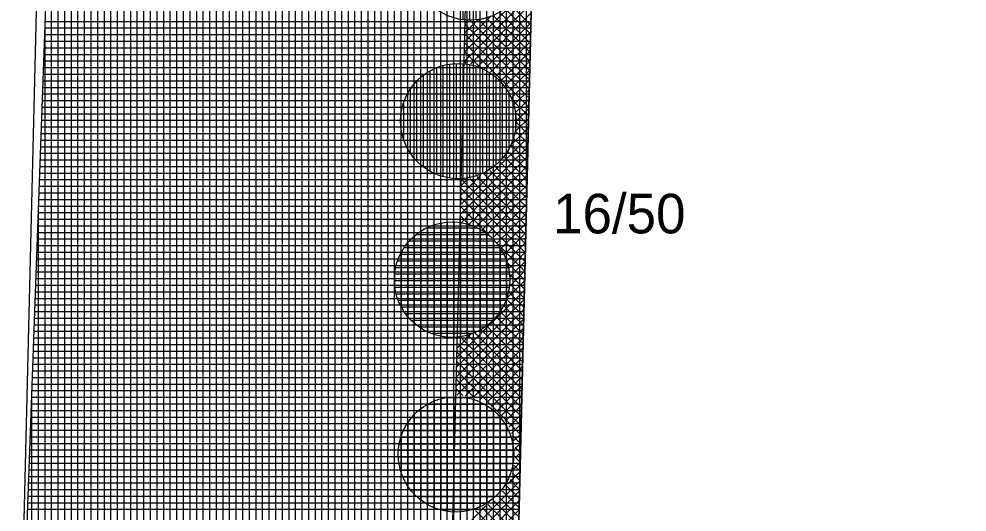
# Model space of a CAD drawing. Extents: x -565346 to -564154, y -1097386 to -1095620.
# Drawn here: x -565040.85 to -565012.1, y -1095843.05 to -1095828.1 of the extents above; entities that cross this region are included whole.
import ezdxf

# ---------------------------------------------------------------- set-up
doc = ezdxf.new("R2010")
doc.units = 0
for name, color, linetype in [('Vrstva 1', 7, 'Continuous'), ('Vrstva 40', 7, 'Continuous'), ('Vrstva 41', 7, 'Continuous'), ('Vrstva 42', 7, 'Continuous'), ('Vrstva 43', 7, 'Continuous'), ('Vrstva 44', 7, 'Continuous')]:
    doc.layers.add(name, color=color, linetype=linetype)

msp = doc.modelspace()

# ---------------------------------------------------------------- linework, layer by layer
at = {"layer": 'Vrstva 1'}
for p, q in [((-565040.85, -1095849.94), (-565040.06, -1095817.34)), ((-565025.24, -1095824.91), (-565025.81, -1095848.33))]:
    msp.add_line(p, q, dxfattribs=at)
at = {"layer": 'Vrstva 41'}
for p, q in [((-565027.342, -1095829.092), (-565025.292, -1095827.042)), ((-565027.349, -1095829.382), (-565025.299, -1095827.332)), ((-565027.142, -1095829.458), (-565025.306, -1095827.621)), ((-565025.329, -1095828.562), (-565026.12, -1095827.77)), ((-565025.322, -1095828.286), (-565025.968, -1095827.64)), ((-565027.335, -1095828.802), (-565026.531, -1095827.998)), ((-565027.328, -1095828.512), (-565026.916, -1095828.1)), ((-565027.321, -1095828.223), (-565027.216, -1095828.117)), ((-565025.362, -1095829.943), (-565027.186, -1095828.119)), ((-565026.924, -1095829.523), (-565025.313, -1095827.911)), ((-565025.356, -1095829.666), (-565026.921, -1095828.101)), ((-565025.349, -1095829.39), (-565026.688, -1095828.051)), ((-565025.342, -1095829.114), (-565026.478, -1095827.978)), ((-565025.335, -1095828.838), (-565026.29, -1095827.884)), ((-565025.369, -1095830.219), (-565027.322, -1095828.266)), ((-565026.726, -1095829.608), (-565025.32, -1095828.201)), ((-565025.376, -1095830.495), (-565027.329, -1095828.542)), ((-565026.547, -1095829.711), (-565025.327, -1095828.491)), ((-565025.382, -1095830.771), (-565027.335, -1095828.818)), ((-565026.385, -1095829.832), (-565025.334, -1095828.781)), ((-565026.907, -1095829.529), (-565027.342, -1095829.094)), ((-565026.239, -1095829.968), (-565025.341, -1095829.071)), ((-565027.285, -1095829.434), (-565027.349, -1095829.37)), ((-565026.108, -1095830.121), (-565025.348, -1095829.361)), ((-565025.994, -1095830.29), (-565025.355, -1095829.651)), ((-565025.898, -1095830.476), (-565025.362, -1095829.941)), ((-565025.823, -1095830.684), (-565025.369, -1095830.231)), ((-565025.389, -1095831.047), (-565025.859, -1095830.577)), ((-565025.771, -1095830.915), (-565025.376, -1095830.521)), ((-565025.396, -1095831.323), (-565025.764, -1095830.955)), ((-565025.747, -1095831.174), (-565025.383, -1095830.81)), ((-565025.777, -1095831.487), (-565025.39, -1095831.1)), ((-565025.403, -1095831.599), (-565025.752, -1095831.25)), ((-565025.885, -1095831.877), (-565025.398, -1095831.39)), ((-565025.409, -1095831.875), (-565025.779, -1095831.506)), ((-565027.455, -1095833.731), (-565025.405, -1095831.68)), ((-565025.416, -1095832.152), (-565025.831, -1095831.736)), ((-565027.462, -1095834.021), (-565025.412, -1095831.97)), ((-565025.43, -1095832.704), (-565026.01, -1095832.123)), ((-565025.423, -1095832.428), (-565025.911, -1095831.939)), ((-565027.444, -1095834.286), (-565025.419, -1095832.26)), ((-565025.443, -1095833.256), (-565026.259, -1095832.44)), ((-565025.436, -1095832.98), (-565026.126, -1095832.29)), ((-565027.214, -1095834.338), (-565025.426, -1095832.55)), ((-565025.456, -1095833.808), (-565026.572, -1095832.693)), ((-565025.45, -1095833.532), (-565026.407, -1095832.575)), ((-565027.448, -1095833.441), (-565026.841, -1095832.833)), ((-565027.441, -1095833.151), (-565027.236, -1095832.946)), ((-565025.483, -1095834.913), (-565027.429, -1095832.967)), ((-565025.477, -1095834.637), (-565027.177, -1095832.937)), ((-565027.006, -1095834.413), (-565025.433, -1095832.84)), ((-565025.47, -1095834.361), (-565026.954, -1095832.877)), ((-565025.463, -1095834.084), (-565026.754, -1095832.794)), ((-565025.49, -1095835.189), (-565027.443, -1095833.236)), ((-565026.821, -1095834.51), (-565025.44, -1095833.13)), ((-565025.497, -1095835.465), (-565027.45, -1095833.512)), ((-565026.653, -1095834.625), (-565025.447, -1095833.42)), ((-565025.503, -1095835.741), (-565027.457, -1095833.788)), ((-565026.502, -1095834.757), (-565025.454, -1095833.709)), ((-565027.181, -1095834.347), (-565027.463, -1095834.064)), ((-565026.366, -1095834.905), (-565025.461, -1095833.999)), ((-565026.248, -1095835.069), (-565025.468, -1095834.289)), ((-565026.146, -1095835.25), (-565025.475, -1095834.579)), ((-565026.064, -1095835.451), (-565025.482, -1095834.869)), ((-565026.005, -1095835.675), (-565025.489, -1095835.159)), ((-565025.51, -1095836.017), (-565026.057, -1095835.471)), ((-565025.976, -1095835.929), (-565025.496, -1095835.449)), ((-565025.996, -1095836.231), (-565025.503, -1095835.739)), ((-565025.517, -1095836.293), (-565025.982, -1095835.829)), ((-565026.079, -1095836.597), (-565025.51, -1095836.029)), ((-565025.524, -1095836.569), (-565025.983, -1095836.11)), ((-565027.568, -1095838.369), (-565025.518, -1095836.319)), ((-565025.53, -1095836.846), (-565026.01, -1095836.366)), ((-565027.575, -1095838.659), (-565025.525, -1095836.608)), ((-565025.544, -1095837.398), (-565026.159, -1095836.783)), ((-565025.537, -1095837.122), (-565026.074, -1095836.585)), ((-565027.582, -1095838.949), (-565025.532, -1095836.898)), ((-565025.551, -1095837.674), (-565026.262, -1095836.962)), ((-565027.589, -1095839.239), (-565025.539, -1095837.188)), ((-565025.564, -1095838.226), (-565026.521, -1095837.27)), ((-565025.557, -1095837.95), (-565026.383, -1095837.124)), ((-565027.57, -1095839.502), (-565025.546, -1095837.478)), ((-565027.561, -1095838.079), (-565027.121, -1095837.639)), ((-565025.584, -1095839.055), (-565027.033, -1095837.605)), ((-565025.577, -1095838.778), (-565026.844, -1095837.512)), ((-565025.571, -1095838.502), (-565026.673, -1095837.4)), ((-565025.604, -1095839.883), (-565027.557, -1095837.93)), ((-565027.554, -1095837.789), (-565027.495, -1095837.73)), ((-565025.598, -1095839.607), (-565027.477, -1095837.727)), ((-565027.311, -1095839.526), (-565025.553, -1095837.768)), ((-565025.591, -1095839.331), (-565027.243, -1095837.678)), ((-565025.611, -1095840.159), (-565027.564, -1095838.206)), ((-565027.079, -1095839.578), (-565025.56, -1095838.058)), ((-565025.618, -1095840.435), (-565027.571, -1095838.482)), ((-565026.872, -1095839.653), (-565025.567, -1095838.348)), ((-565025.624, -1095840.711), (-565027.578, -1095838.758)), ((-565026.684, -1095839.747), (-565025.574, -1095838.638)), ((-565027.025, -1095839.594), (-565027.584, -1095839.034)), ((-565026.514, -1095839.861), (-565025.581, -1095838.928)), ((-565027.388, -1095839.514), (-565027.591, -1095839.31)), ((-565026.361, -1095839.99), (-565025.588, -1095839.218)), ((-565026.223, -1095840.135), (-565025.595, -1095839.507)), ((-565026.101, -1095840.296), (-565025.602, -1095839.797)), ((-565025.996, -1095840.474), (-565025.609, -1095840.087)), ((-565025.909, -1095840.67), (-565025.616, -1095840.377)), ((-565025.631, -1095840.987), (-565025.884, -1095840.735)), ((-565025.842, -1095840.885), (-565025.623, -1095840.667)), ((-565025.638, -1095841.263), (-565025.804, -1095841.098)), ((-565025.8, -1095841.127), (-565025.63, -1095840.957)), ((-565025.802, -1095841.412), (-565025.638, -1095841.247)), ((-565025.645, -1095841.54), (-565025.799, -1095841.385)), ((-565025.846, -1095841.738), (-565025.645, -1095841.537)), ((-565025.651, -1095841.816), (-565025.826, -1095841.641)), ((-565026.034, -1095842.209), (-565025.652, -1095841.827)), ((-565025.658, -1095842.092), (-565025.882, -1095841.868)), ((-565027.709, -1095844.167), (-565025.659, -1095842.117)), ((-565025.665, -1095842.368), (-565025.963, -1095842.069)), ((-565027.688, -1095844.429), (-565025.666, -1095842.406)), ((-565025.678, -1095842.92), (-565026.18, -1095842.419)), ((-565025.672, -1095842.644), (-565026.063, -1095842.253)), ((-565027.403, -1095844.427), (-565025.673, -1095842.696)), ((-565025.698, -1095843.749), (-565026.625, -1095842.822)), ((-565025.692, -1095843.472), (-565026.461, -1095842.704)), ((-565025.685, -1095843.196), (-565026.312, -1095842.569)), ((-565027.702, -1095843.877), (-565026.689, -1095842.864)), ((-565027.154, -1095844.461), (-565025.68, -1095842.986)), ((-565025.712, -1095844.301), (-565027.006, -1095843.007)), ((-565025.705, -1095844.025), (-565026.806, -1095842.924))]:
    msp.add_line(p, q, dxfattribs=at)
at = {"layer": 'Vrstva 42'}
msp.add_lwpolyline([(-565027.198, -1095823.179), (-565025.19, -1095822.881), (-565025.81, -1095848.33), (-565027.809, -1095848.281)], close=True, dxfattribs=at)
at = {"layer": 'Vrstva 43'}
for p, q in [((-565027.07, -1095810.019), (-565027.07, -1095848.465)), ((-565026.87, -1095809.989), (-565026.87, -1095848.443)), ((-565026.67, -1095809.959), (-565026.67, -1095848.422)), ((-565026.47, -1095809.929), (-565026.47, -1095848.401)), ((-565026.27, -1095809.9), (-565026.27, -1095848.379)), ((-565026.07, -1095809.87), (-565026.07, -1095848.358)), ((-565025.87, -1095809.84), (-565025.87, -1095848.336)), ((-565025.67, -1095809.811), (-565025.67, -1095842.578)), ((-565025.47, -1095809.781), (-565025.47, -1095834.36)), ((-565029.07, -1095810.316), (-565029.07, -1095848.679)), ((-565028.87, -1095810.286), (-565028.87, -1095848.658)), ((-565028.67, -1095810.256), (-565028.67, -1095848.636)), ((-565028.47, -1095810.226), (-565028.47, -1095848.615)), ((-565028.27, -1095810.197), (-565028.27, -1095848.593)), ((-565028.07, -1095810.167), (-565028.07, -1095848.572)), ((-565027.87, -1095810.137), (-565027.87, -1095848.551)), ((-565027.67, -1095810.108), (-565027.67, -1095848.529)), ((-565027.47, -1095810.078), (-565027.47, -1095848.508)), ((-565027.27, -1095810.048), (-565027.27, -1095848.486)), ((-565031.07, -1095810.613), (-565031.07, -1095848.893)), ((-565030.87, -1095810.583), (-565030.87, -1095848.872)), ((-565030.67, -1095810.553), (-565030.67, -1095848.85)), ((-565030.47, -1095810.523), (-565030.47, -1095848.829)), ((-565030.27, -1095810.494), (-565030.27, -1095848.807)), ((-565030.07, -1095810.464), (-565030.07, -1095848.786)), ((-565029.87, -1095810.434), (-565029.87, -1095848.765)), ((-565029.67, -1095810.405), (-565029.67, -1095848.743)), ((-565029.47, -1095810.375), (-565029.47, -1095848.722)), ((-565029.27, -1095810.345), (-565029.27, -1095848.7)), ((-565032.87, -1095810.88), (-565032.87, -1095849.086)), ((-565032.67, -1095810.85), (-565032.67, -1095849.064)), ((-565032.47, -1095810.82), (-565032.47, -1095849.043)), ((-565032.27, -1095810.791), (-565032.27, -1095849.022)), ((-565032.07, -1095810.761), (-565032.07, -1095849)), ((-565031.87, -1095810.731), (-565031.87, -1095848.979)), ((-565031.67, -1095810.702), (-565031.67, -1095848.957)), ((-565031.47, -1095810.672), (-565031.47, -1095848.936)), ((-565031.27, -1095810.642), (-565031.27, -1095848.914)), ((-565034.87, -1095811.177), (-565034.87, -1095849.3)), ((-565034.67, -1095811.147), (-565034.67, -1095849.278)), ((-565034.47, -1095811.117), (-565034.47, -1095849.257)), ((-565034.27, -1095811.088), (-565034.27, -1095849.236)), ((-565034.07, -1095811.058), (-565034.07, -1095849.214)), ((-565033.87, -1095811.028), (-565033.87, -1095849.193)), ((-565033.67, -1095810.999), (-565033.67, -1095849.171)), ((-565033.47, -1095810.969), (-565033.47, -1095849.15)), ((-565033.27, -1095810.939), (-565033.27, -1095849.129)), ((-565033.07, -1095810.91), (-565033.07, -1095849.107)), ((-565036.87, -1095811.474), (-565036.87, -1095849.514)), ((-565036.67, -1095811.444), (-565036.67, -1095849.493)), ((-565036.47, -1095811.414), (-565036.47, -1095849.471)), ((-565036.27, -1095811.385), (-565036.27, -1095849.45)), ((-565036.07, -1095811.355), (-565036.07, -1095849.428)), ((-565035.87, -1095811.325), (-565035.87, -1095849.407)), ((-565035.67, -1095811.296), (-565035.67, -1095849.385)), ((-565035.47, -1095811.266), (-565035.47, -1095849.364)), ((-565035.27, -1095811.236), (-565035.27, -1095849.343)), ((-565035.07, -1095811.207), (-565035.07, -1095849.321)), ((-565038.67, -1095811.741), (-565038.67, -1095849.707)), ((-565038.47, -1095811.711), (-565038.47, -1095849.685)), ((-565038.27, -1095811.682), (-565038.27, -1095849.664)), ((-565038.07, -1095811.652), (-565038.07, -1095849.642)), ((-565037.87, -1095811.622), (-565037.87, -1095849.621)), ((-565037.67, -1095811.593), (-565037.67, -1095849.6)), ((-565037.47, -1095811.563), (-565037.47, -1095849.578)), ((-565037.27, -1095811.533), (-565037.27, -1095849.557)), ((-565037.07, -1095811.504), (-565037.07, -1095849.535)), ((-565039.47, -1095811.86), (-565039.47, -1095849.792)), ((-565039.27, -1095811.83), (-565039.27, -1095849.771)), ((-565039.07, -1095811.801), (-565039.07, -1095849.749)), ((-565038.87, -1095811.771), (-565038.87, -1095849.728)), ((-565039.67, -1095817.379), (-565039.67, -1095849.814)), ((-565039.87, -1095822.898), (-565039.87, -1095849.835)), ((-565040.07, -1095828.417), (-565040.07, -1095849.857)), ((-565025.324, -1095828.38), (-565040.069, -1095828.38)), ((-565025.32, -1095828.18), (-565040.061, -1095828.18)), ((-565025.329, -1095828.58), (-565040.076, -1095828.58)), ((-565025.339, -1095828.98), (-565040.09, -1095828.98)), ((-565025.334, -1095828.78), (-565040.083, -1095828.78)), ((-565025.344, -1095829.18), (-565040.098, -1095829.18)), ((-565025.354, -1095829.58), (-565040.112, -1095829.58)), ((-565025.349, -1095829.38), (-565040.105, -1095829.38)), ((-565025.359, -1095829.78), (-565040.119, -1095829.78)), ((-565025.363, -1095829.98), (-565040.127, -1095829.98)), ((-565025.373, -1095830.38), (-565040.141, -1095830.38)), ((-565025.368, -1095830.18), (-565040.134, -1095830.18)), ((-565025.378, -1095830.58), (-565040.148, -1095830.58)), ((-565025.388, -1095830.98), (-565040.163, -1095830.98)), ((-565025.383, -1095830.78), (-565040.156, -1095830.78)), ((-565025.393, -1095831.18), (-565040.17, -1095831.18)), ((-565025.402, -1095831.58), (-565040.185, -1095831.58)), ((-565025.397, -1095831.38), (-565040.177, -1095831.38)), ((-565025.407, -1095831.78), (-565040.192, -1095831.78)), ((-565025.417, -1095832.18), (-565040.206, -1095832.18)), ((-565025.412, -1095831.98), (-565040.199, -1095831.98)), ((-565025.422, -1095832.38), (-565040.214, -1095832.38)), ((-565025.427, -1095832.58), (-565040.221, -1095832.58)), ((-565025.436, -1095832.98), (-565040.235, -1095832.98)), ((-565025.432, -1095832.78), (-565040.228, -1095832.78)), ((-565025.441, -1095833.18), (-565040.243, -1095833.18)), ((-565025.451, -1095833.58), (-565040.257, -1095833.58)), ((-565025.446, -1095833.38), (-565040.25, -1095833.38)), ((-565025.456, -1095833.78), (-565040.264, -1095833.78)), ((-565025.466, -1095834.18), (-565040.279, -1095834.18)), ((-565025.461, -1095833.98), (-565040.272, -1095833.98)), ((-565040.27, -1095833.935), (-565040.27, -1095849.878)), ((-565025.47, -1095834.38), (-565040.286, -1095834.38)), ((-565025.475, -1095834.58), (-565040.293, -1095834.58)), ((-565025.485, -1095834.98), (-565040.308, -1095834.98)), ((-565025.48, -1095834.78), (-565040.301, -1095834.78)), ((-565025.49, -1095835.18), (-565040.315, -1095835.18)), ((-565025.5, -1095835.58), (-565040.33, -1095835.58)), ((-565025.495, -1095835.38), (-565040.322, -1095835.38)), ((-565025.505, -1095835.78), (-565040.337, -1095835.78)), ((-565025.514, -1095836.18), (-565040.351, -1095836.18)), ((-565025.509, -1095835.98), (-565040.344, -1095835.98)), ((-565025.519, -1095836.38), (-565040.359, -1095836.38)), ((-565025.529, -1095836.78), (-565040.373, -1095836.78)), ((-565025.524, -1095836.58), (-565040.366, -1095836.58)), ((-565025.534, -1095836.98), (-565040.38, -1095836.98)), ((-565025.539, -1095837.18), (-565040.388, -1095837.18)), ((-565025.548, -1095837.58), (-565040.402, -1095837.58)), ((-565025.543, -1095837.38), (-565040.395, -1095837.38)), ((-565025.553, -1095837.78), (-565040.409, -1095837.78)), ((-565025.563, -1095838.18), (-565040.424, -1095838.18)), ((-565025.558, -1095837.98), (-565040.417, -1095837.98)), ((-565025.568, -1095838.38), (-565040.431, -1095838.38)), ((-565025.578, -1095838.78), (-565040.446, -1095838.78)), ((-565025.573, -1095838.58), (-565040.438, -1095838.58)), ((-565025.582, -1095838.98), (-565040.453, -1095838.98)), ((-565025.587, -1095839.18), (-565040.46, -1095839.18)), ((-565025.597, -1095839.58), (-565040.475, -1095839.58)), ((-565040.47, -1095839.454), (-565040.47, -1095849.899)), ((-565025.592, -1095839.38), (-565040.467, -1095839.38)), ((-565025.602, -1095839.78), (-565040.482, -1095839.78)), ((-565025.612, -1095840.18), (-565040.496, -1095840.18)), ((-565025.607, -1095839.98), (-565040.489, -1095839.98)), ((-565025.617, -1095840.38), (-565040.504, -1095840.38)), ((-565025.626, -1095840.78), (-565040.518, -1095840.78)), ((-565025.621, -1095840.58), (-565040.511, -1095840.58)), ((-565025.631, -1095840.98), (-565040.525, -1095840.98)), ((-565025.641, -1095841.38), (-565040.54, -1095841.38)), ((-565025.636, -1095841.18), (-565040.533, -1095841.18)), ((-565025.646, -1095841.58), (-565040.547, -1095841.58)), ((-565025.651, -1095841.78), (-565040.554, -1095841.78)), ((-565025.66, -1095842.18), (-565040.569, -1095842.18)), ((-565025.655, -1095841.98), (-565040.562, -1095841.98)), ((-565025.665, -1095842.38), (-565040.576, -1095842.38)), ((-565025.675, -1095842.78), (-565040.591, -1095842.78)), ((-565025.67, -1095842.58), (-565040.583, -1095842.58)), ((-565025.68, -1095842.98), (-565040.598, -1095842.98))]:
    msp.add_line(p, q, dxfattribs=at)
msp.add_lwpolyline([(-564584.17, -1095730.99), (-564361.01, -1095672.63), (-564329.81, -1095662.26), (-564326.21, -1095642.73), (-564394.52, -1095662.95), (-564454.33, -1095677.56), (-564516.6, -1095690.89), (-564574.04, -1095705.03), (-564590.74, -1095715.12), (-564631.48, -1095731.18), (-564693.31, -1095752.31), (-564772.2, -1095768.91), (-564879.81, -1095788.15), (-565039.47, -1095811.86), (-565040.85, -1095849.94), (-565025.81, -1095848.33), (-565025.24, -1095824.91), (-564877.52, -1095802.97), (-564694, -1095767.75), (-564603.8, -1095739.23), (-564594.74, -1095734.52)], close=True, dxfattribs=at)
at = {"layer": 'Vrstva 44'}
for p, q in [((-565027.39, -1095824.651), (-565027.39, -1095828.119)), ((-565027.19, -1095824.636), (-565027.19, -1095828.133)), ((-565026.99, -1095824.643), (-565026.99, -1095828.124)), ((-565026.848, -1095829.58), (-565028.196, -1095829.58)), ((-565028.19, -1095829.577), (-565028.19, -1095832.812)), ((-565027.99, -1095829.507), (-565027.99, -1095832.88)), ((-565027.79, -1095829.466), (-565027.79, -1095832.922)), ((-565027.59, -1095829.447), (-565027.59, -1095832.942)), ((-565027.39, -1095829.451), (-565027.39, -1095832.938)), ((-565027.19, -1095829.477), (-565027.19, -1095832.91)), ((-565026.99, -1095829.528), (-565026.99, -1095832.858)), ((-565028.59, -1095829.806), (-565028.59, -1095832.581)), ((-565026.496, -1095829.78), (-565028.553, -1095829.78)), ((-565028.39, -1095829.675), (-565028.39, -1095832.713)), ((-565026.79, -1095829.608), (-565026.79, -1095832.781)), ((-565026.59, -1095829.716), (-565026.59, -1095832.672)), ((-565026.39, -1095829.863), (-565026.39, -1095832.524)), ((-565028.79, -1095829.988), (-565028.79, -1095832.4)), ((-565026.266, -1095829.98), (-565028.782, -1095829.98)), ((-565026.19, -1095830.062), (-565026.19, -1095832.324)), ((-565025.977, -1095830.38), (-565029.071, -1095830.38)), ((-565028.99, -1095830.242), (-565028.99, -1095832.146)), ((-565026.099, -1095830.18), (-565028.95, -1095830.18)), ((-565025.99, -1095830.353), (-565025.99, -1095832.032)), ((-565029.19, -1095830.664), (-565029.19, -1095831.726)), ((-565025.888, -1095830.58), (-565029.162, -1095830.58)), ((-565025.787, -1095830.98), (-565029.259, -1095830.98)), ((-565025.825, -1095830.78), (-565029.224, -1095830.78)), ((-565025.79, -1095830.965), (-565025.79, -1095831.414)), ((-565025.775, -1095831.18), (-565029.272, -1095831.18)), ((-565025.786, -1095831.38), (-565029.263, -1095831.38)), ((-565025.819, -1095831.58), (-565029.23, -1095831.58)), ((-565025.876, -1095831.78), (-565029.172, -1095831.78)), ((-565025.962, -1095831.98), (-565029.086, -1095831.98)), ((-565026.081, -1095832.18), (-565028.969, -1095832.18)), ((-565026.238, -1095832.38), (-565028.808, -1095832.38)), ((-565026.457, -1095832.58), (-565028.591, -1095832.58)), ((-565026.787, -1095832.78), (-565028.259, -1095832.78)), ((-565026.933, -1095834.44), (-565028.499, -1095834.44)), ((-565028.46, -1095834.423), (-565028.46, -1095837.585)), ((-565028.26, -1095834.343), (-565028.26, -1095837.665)), ((-565028.06, -1095834.29), (-565028.06, -1095837.718)), ((-565027.86, -1095834.26), (-565027.86, -1095837.746)), ((-565027.66, -1095834.256), (-565027.66, -1095837.751)), ((-565027.46, -1095834.274), (-565027.46, -1095837.734)), ((-565027.26, -1095834.316), (-565027.26, -1095837.694)), ((-565027.06, -1095834.382), (-565027.06, -1095837.625)), ((-565026.86, -1095834.478), (-565026.86, -1095837.529)), ((-565028.86, -1095834.684), (-565028.86, -1095837.324)), ((-565026.619, -1095834.64), (-565028.808, -1095834.64)), ((-565028.66, -1095834.533), (-565028.66, -1095837.476)), ((-565026.66, -1095834.61), (-565026.66, -1095837.4)), ((-565026.255, -1095835.04), (-565029.172, -1095835.04)), ((-565029.06, -1095834.888), (-565029.06, -1095837.121)), ((-565026.41, -1095834.84), (-565029.021, -1095834.84)), ((-565026.46, -1095834.785), (-565026.46, -1095837.222)), ((-565026.26, -1095835.032), (-565026.26, -1095836.974)), ((-565026.142, -1095835.24), (-565029.287, -1095835.24)), ((-565029.26, -1095835.188), (-565029.26, -1095836.82)), ((-565026.059, -1095835.44), (-565029.37, -1095835.44)), ((-565026.06, -1095835.436), (-565026.06, -1095836.57)), ((-565029.46, -1095835.893), (-565029.46, -1095836.106)), ((-565025.974, -1095835.84), (-565029.455, -1095835.84)), ((-565026.003, -1095835.64), (-565029.424, -1095835.64)), ((-565025.967, -1095836.04), (-565029.462, -1095836.04)), ((-565025.982, -1095836.24), (-565029.448, -1095836.24)), ((-565026.02, -1095836.44), (-565029.408, -1095836.44)), ((-565026.085, -1095836.64), (-565029.342, -1095836.64)), ((-565026.179, -1095836.84), (-565029.25, -1095836.84)), ((-565026.305, -1095837.04), (-565029.123, -1095837.04)), ((-565026.478, -1095837.24), (-565028.951, -1095837.24)), ((-565026.717, -1095837.44), (-565028.711, -1095837.44)), ((-565027.095, -1095837.64), (-565028.332, -1095837.64)), ((-565028.06, -1095839.617), (-565028.06, -1095842.99)), ((-565027.242, -1095839.59), (-565027.94, -1095839.59)), ((-565027.86, -1095839.576), (-565027.86, -1095843.032)), ((-565027.66, -1095839.557), (-565027.66, -1095843.052)), ((-565027.46, -1095839.561), (-565027.46, -1095843.048)), ((-565027.26, -1095839.587), (-565027.26, -1095843.02)), ((-565027.06, -1095839.638), (-565027.06, -1095842.968)), ((-565028.66, -1095839.916), (-565028.66, -1095842.691)), ((-565026.72, -1095839.79), (-565028.468, -1095839.79)), ((-565028.46, -1095839.785), (-565028.46, -1095842.823)), ((-565028.26, -1095839.687), (-565028.26, -1095842.922)), ((-565026.86, -1095839.718), (-565026.86, -1095842.891)), ((-565026.66, -1095839.826), (-565026.66, -1095842.782)), ((-565026.245, -1095840.19), (-565028.941, -1095840.19)), ((-565028.86, -1095840.098), (-565028.86, -1095842.51)), ((-565026.441, -1095839.99), (-565028.747, -1095839.99)), ((-565026.46, -1095839.973), (-565026.46, -1095842.634)), ((-565026.26, -1095840.172), (-565026.26, -1095842.434)), ((-565026.104, -1095840.39), (-565029.085, -1095840.39)), ((-565029.06, -1095840.352), (-565029.06, -1095842.256)), ((-565026.06, -1095840.463), (-565026.06, -1095842.142)), ((-565025.922, -1095840.79), (-565029.265, -1095840.79)), ((-565029.26, -1095840.774), (-565029.26, -1095841.836)), ((-565025.997, -1095840.59), (-565029.191, -1095840.59)), ((-565025.875, -1095840.99), (-565029.314, -1095840.99)), ((-565025.86, -1095841.075), (-565025.86, -1095841.524)), ((-565025.85, -1095841.19), (-565029.34, -1095841.19)), ((-565025.848, -1095841.39), (-565029.341, -1095841.39)), ((-565025.868, -1095841.59), (-565029.319, -1095841.59)), ((-565025.914, -1095841.79), (-565029.273, -1095841.79)), ((-565025.986, -1095841.99), (-565029.203, -1095841.99)), ((-565026.086, -1095842.19), (-565029.102, -1095842.19)), ((-565026.224, -1095842.39), (-565028.964, -1095842.39)), ((-565026.408, -1095842.59), (-565028.779, -1095842.59)), ((-565026.671, -1095842.79), (-565028.516, -1095842.79)), ((-565027.128, -1095842.99), (-565028.06, -1095842.99))]:
    msp.add_line(p, q, dxfattribs=at)
for centre in [(-565027.164, -1095826.384), (-565027.524, -1095831.194), (-565027.714, -1095836.004), (-565027.594, -1095841.304)]:
    msp.add_circle(centre, 1.75, dxfattribs=at)

# ---------------------------------------------------------------- texts
at = {"layer": 'Vrstva 40'}
msp.add_text('16/50', height=1.2, dxfattribs=at).set_placement((-565024.65, -1095834.6))

doc.saveas('drawing.dxf')
